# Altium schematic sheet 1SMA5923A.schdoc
size 127 x 101 mm
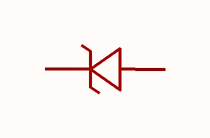
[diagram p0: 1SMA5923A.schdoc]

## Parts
D?  1sma5923a  [SMA_L4.4-W2.8-LS5.4-RD]  (value not drawn)

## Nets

Not connected (* = marked no-connect by the designer): D? 1(K) 2(A)

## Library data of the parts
D? = 1sma5923a: 二极管配置:1个独立式;稳压值(标称值):8.2V;稳压值(范围):7.79V~8.61V;耗散功率(Pd):1.5W;; Manufacturer: CJ(江苏长电/长晶); AddInBom: yes; ModelId: 4f1e9ef2303f48b48aa8ce0cacf8d7b1; ModelTransform: 204.724,102.362,0,0,0,0,0,0,0; Diode Configuration: 1个独立式; Zener Voltage(Nom): 8.2V; Reverse Leakage Current (Ir): 2.5uA@6.5V; Pd - Power Dissipation: 1.5W; Impedance(Zzt): 3.5Ω; Impedance(Zzk): 400Ω; Operating Junction Temperature Range: -55℃~+150℃; Tolerance: ±5%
